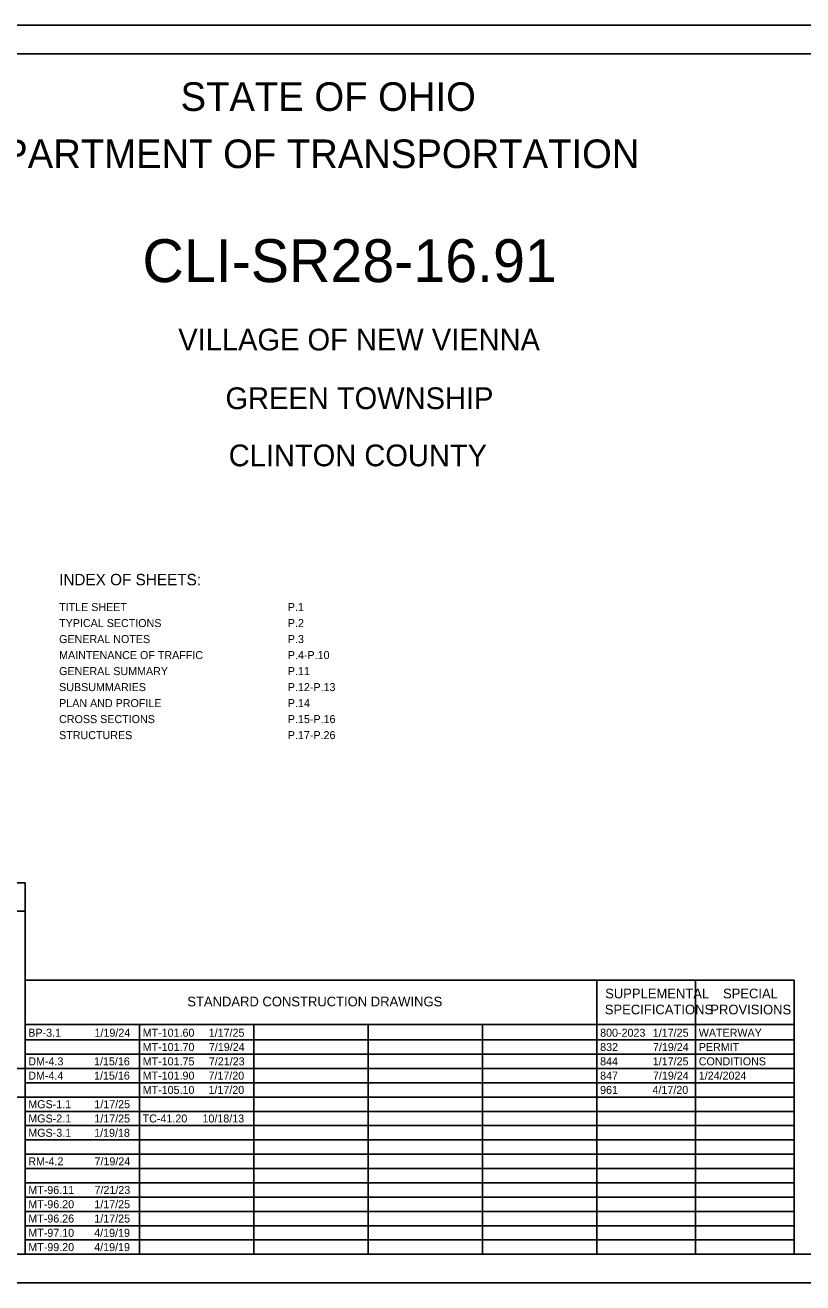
# Model space of a CAD drawing. Extents: x 0 to 40.9, y 0 to 22.
# Drawn here: x 11.25 to 24.85, y 0 to 22 of the extents above; entities that cross this region are included whole.
import ezdxf

# ---------------------------------------------------------------- set-up
doc = ezdxf.new("R2010")
doc.units = 0
for name, color, linetype in [('SH_Border', 7, 'Continuous'), ('SH_Cut_Line', 7, 'Continuous'), ('SH_Data', 7, 'Continuous'), ('SH_Text', 7, 'Continuous')]:
    doc.layers.add(name, color=color, linetype=linetype)

msp = doc.modelspace()

# ---------------------------------------------------------------- linework, layer by layer
at = {"layer": 'SH_Cut_Line'}
for p, q in [((8.45, 7), (11.25, 7)), ((11.25, 0.5), (11.25, 7)), ((8.45, 6.5), (11.25, 6.5)), ((11.25, 5.292), (24.7, 5.292)), ((11.25, 0.5), (11.25, 5.292)), ((21.25, 0.5), (21.25, 5.292)), ((22.975, 0.5), (22.975, 5.292)), ((24.7, 0.5), (24.7, 5.292)), ((11.25, 4.521), (24.7, 4.521)), ((13.25, 0.5), (13.25, 4.521)), ((15.25, 0.5), (15.25, 4.521)), ((17.25, 0.5), (17.25, 4.521)), ((19.25, 0.5), (19.25, 4.521)), ((11.25, 4.25), (24.7, 4.25)), ((11.25, 4), (24.7, 4)), ((8.45, 3.75), (11.25, 3.75)), ((11.25, 3.75), (24.7, 3.75)), ((11.25, 3.5), (24.7, 3.5)), ((8.45, 3.25), (11.25, 3.25)), ((11.25, 3.25), (24.7, 3.25)), ((11.25, 3), (24.7, 3)), ((11.25, 2.75), (24.7, 2.75)), ((11.25, 2.5), (24.7, 2.5)), ((11.25, 2.25), (24.7, 2.25)), ((11.25, 2), (24.7, 2)), ((11.25, 1.75), (24.7, 1.75)), ((11.25, 1.5), (24.7, 1.5)), ((11.25, 1.25), (24.7, 1.25)), ((11.25, 1), (24.7, 1)), ((11.25, 0.75), (24.7, 0.75))]:
    msp.add_line(p, q, dxfattribs=at)
at = {"layer": 'SH_Data'}
msp.add_lwpolyline([(0, 0), (34, 0), (34, 22), (0, 22)], close=True, dxfattribs=at)
at = {"layer": 'SH_Text'}
msp.add_lwpolyline([(1.5, 21.5), (33.5, 21.5), (33.5, 0.5), (1.5, 0.5)], close=True, dxfattribs=at)

# ---------------------------------------------------------------- texts
at = {"layer": 'SH_Border'}
for s, height, p in [('STATE OF OHIO', 0.5, (13.968, 20.5)), ('DEPARTMENT OF TRANSPORTATION', 0.5, (9.92, 19.5)), ('CLI-SR28-16.91', 0.75, (13.301, 17.505)), ('VILLAGE OF NEW VIENNA', 0.38, (13.928, 16.31)), ('GREEN TOWNSHIP', 0.38, (14.753, 15.284)), ('CLINTON COUNTY', 0.38, (14.81, 14.284)), ('INDEX OF SHEETS:', 0.2, (11.844, 12.202)), ('TITLE SHEET', 0.14, (11.844, 11.751)), ('P.1', 0.14, (15.844, 11.751)), ('TYPICAL SECTIONS', 0.14, (11.844, 11.471)), ('P.2', 0.14, (15.844, 11.471)), ('GENERAL NOTES', 0.14, (11.844, 11.191)), ('P.3', 0.14, (15.844, 11.191)), ('MAINTENANCE OF TRAFFIC', 0.14, (11.844, 10.911)), ('P.4-P.10', 0.14, (15.844, 10.911)), ('GENERAL SUMMARY', 0.14, (11.844, 10.631)), ('P.11', 0.14, (15.844, 10.631)), ('SUBSUMMARIES', 0.14, (11.844, 10.351)), ('P.12-P.13', 0.14, (15.844, 10.351)), ('PLAN AND PROFILE', 0.14, (11.844, 10.071)), ('P.14', 0.14, (15.844, 10.071)), ('CROSS SECTIONS', 0.14, (11.844, 9.791)), ('P.15-P.16', 0.14, (15.844, 9.791)), ('STRUCTURES', 0.14, (11.844, 9.511)), ('P.17-P.26', 0.14, (15.844, 9.511)), ('SUPPLEMENTAL', 0.17, (21.393, 4.976)), ('SPECIAL', 0.17, (23.454, 4.976)), ('STANDARD CONSTRUCTION DRAWINGS', 0.17, (14.086, 4.836)), ('SPECIFICATIONS', 0.17, (21.387, 4.696)), ('PROVISIONS', 0.17, (23.232, 4.696)), ('WATERWAY', 0.14, (23.03, 4.305)), ('PERMIT', 0.14, (23.03, 4.055)), ('CONDITIONS', 0.14, (23.03, 3.805)), ('1/24/2024', 0.14, (23.03, 3.555))]:
    msp.add_text(s, height=height, dxfattribs=at).set_placement(p)
at = {"layer": 'SH_Cut_Line'}
for s, p in [('BP-3.1', (11.305, 4.305)), ('1/19/24', (12.463, 4.305)), ('MT-101.60', (13.305, 4.305)), ('1/17/25', (14.46, 4.305)), ('800-2023', (21.305, 4.305)), ('1/17/25', (22.226, 4.305)), ('MT-101.70', (13.305, 4.055)), ('7/19/24', (14.463, 4.055)), ('832', (21.305, 4.055)), ('7/19/24', (22.229, 4.055)), ('DM-4.3', (11.305, 3.805)), ('1/15/16', (12.455, 3.805)), ('MT-101.75', (13.305, 3.805)), ('7/21/23', (14.463, 3.805)), ('844', (21.305, 3.805)), ('1/17/25', (22.226, 3.805)), ('DM-4.4', (11.305, 3.555)), ('1/15/16', (12.455, 3.555)), ('MT-101.90', (13.305, 3.555)), ('7/17/20', (14.456, 3.555)), ('847', (21.305, 3.555)), ('7/19/24', (22.229, 3.555)), ('MT-105.10', (13.305, 3.305)), ('1/17/20', (14.456, 3.305)), ('961', (21.305, 3.305)), ('4/17/20', (22.221, 3.305)), ('MGS-1.1', (11.305, 3.055)), ('1/17/25', (12.46, 3.055)), ('MGS-2.1', (11.305, 2.805)), ('1/17/25', (12.46, 2.805)), ('TC-41.20', (13.305, 2.805)), ('10/18/13', (14.351, 2.805)), ('MGS-3.1', (11.305, 2.555)), ('1/19/18', (12.457, 2.555)), ('7/19/24', (12.463, 2.055)), ('RM-4.2', (11.305, 2.055)), ('MT-96.11', (11.305, 1.555)), ('7/21/23', (12.463, 1.555)), ('MT-96.20', (11.305, 1.305)), ('1/17/25', (12.46, 1.305)), ('MT-96.26', (11.305, 1.055)), ('1/17/25', (12.46, 1.055)), ('MT-97.10', (11.305, 0.805)), ('4/19/19', (12.458, 0.805)), ('MT-99.20', (11.305, 0.555)), ('4/19/19', (12.458, 0.555))]:
    msp.add_text(s, height=0.14, dxfattribs=at).set_placement(p)

doc.saveas('drawing.dxf')
